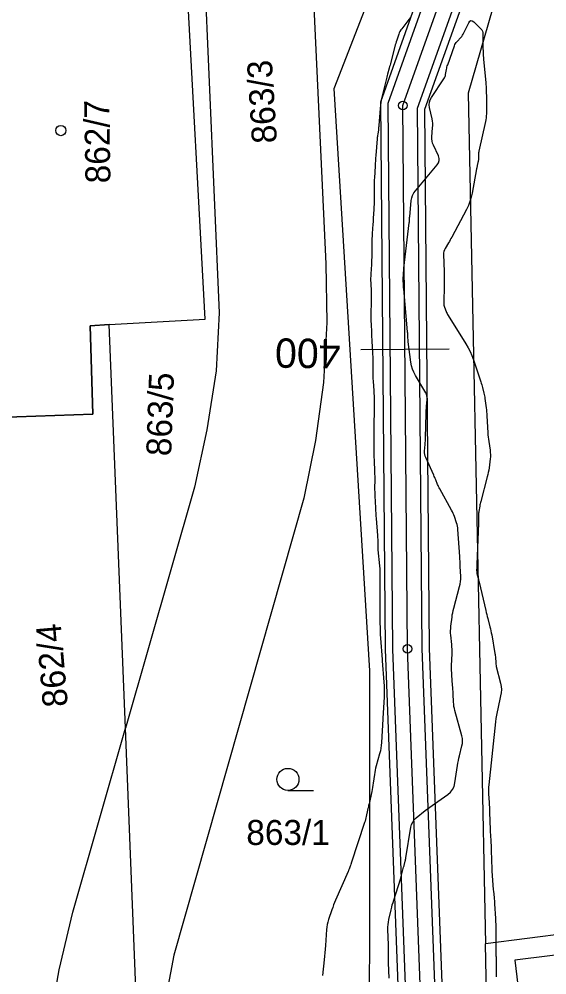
# Model space of a CAD drawing. Extents: x -534481 to -534256, y -1190577 to -1190138.
# Drawn here: x -534359.12 to -534341.14, y -1190186.56 to -1190154.02 of the extents above; entities that cross this region are included whole.
import ezdxf

# ---------------------------------------------------------------- set-up
doc = ezdxf.new("R2010")
doc.units = 0
for name, color, linetype in [('0_kroužky', 7, 'Continuous'), ('30', 7, 'Continuous'), ('31', 7, 'Continuous'), ('_N_osa', 7, 'Continuous'), ('_N_text', 7, 'Continuous'), ('_tenka', 7, 'Continuous'), ('Hranice parcel', 7, 'Continuous'), ('Parcelní čísla', 7, 'Continuous'), ('Polygon budovy', 7, 'Continuous'), ('Značky budov', 7, 'Continuous'), ('Značky kultur', 7, 'Continuous')]:
    doc.layers.add(name, color=color, linetype=linetype)

msp = doc.modelspace()

# ---------------------------------------------------------------- linework, layer by layer
at = {"layer": '0_kroužky'}
for centre in [(-534346.05, -1190156.962), (-534346.05, -1190156.962), (-534346.05, -1190156.962), (-534346.05, -1190156.962), (-534346.05, -1190156.962), (-534346.05, -1190156.962), (-534345.89, -1190175.458), (-534345.89, -1190175.458), (-534345.89, -1190175.458), (-534345.89, -1190175.458), (-534345.89, -1190175.458), (-534345.89, -1190175.458)]:
    msp.add_circle(centre, 0.15, dxfattribs=at)
at = {"layer": '30'}
msp.add_lwpolyline([(-534346.521, -1190186.667), (-534346.539, -1190186.147), (-534346.541, -1190186.096), (-534346.542, -1190186.045), (-534346.542, -1190185.994), (-534346.541, -1190185.943), (-534346.537, -1190185.739), (-534346.537, -1190185.688), (-534346.537, -1190185.637), (-534346.538, -1190185.586), (-534346.539, -1190185.535), (-534346.56, -1190185.016), (-534346.56, -1190184.93), (-534346.555, -1190184.846), (-534346.544, -1190184.761), (-534346.528, -1190184.678), (-534346.45, -1190184.344), (-534346.43, -1190184.26), (-534346.408, -1190184.177), (-534346.385, -1190184.095), (-534346.36, -1190184.013), (-534346.135, -1190183.297), (-534346.121, -1190183.253), (-534346.107, -1190183.208), (-534346.095, -1190183.162), (-534346.082, -1190183.117), (-534346.024, -1190182.898), (-534346.017, -1190182.871), (-534346.01, -1190182.844), (-534346.003, -1190182.818), (-534345.997, -1190182.791), (-534345.97, -1190182.684), (-534345.964, -1190182.657), (-534345.958, -1190182.63), (-534345.953, -1190182.603), (-534345.948, -1190182.576), (-534345.775, -1190181.533), (-534345.752, -1190181.441), (-534345.713, -1190181.357), (-534345.66, -1190181.282), (-534345.592, -1190181.216), (-534345.288, -1190180.968), (-534345.212, -1190180.907), (-534345.135, -1190180.848), (-534345.056, -1190180.789), (-534344.976, -1190180.733), (-534344.52, -1190180.416), (-534344.427, -1190180.338), (-534344.356, -1190180.247), (-534344.306, -1190180.143), (-534344.277, -1190180.026), (-534344.189, -1190179.436), (-534344.175, -1190179.351), (-534344.159, -1190179.266), (-534344.141, -1190179.181), (-534344.121, -1190179.097), (-534344.037, -1190178.761), (-534344.022, -1190178.677), (-534344.017, -1190178.593), (-534344.023, -1190178.509), (-534344.041, -1190178.425), (-534344.279, -1190177.556), (-534344.296, -1190177.487), (-534344.309, -1190177.417), (-534344.318, -1190177.346), (-534344.323, -1190177.275), (-534344.337, -1190176.988), (-534344.34, -1190176.916), (-534344.345, -1190176.845), (-534344.349, -1190176.773), (-534344.355, -1190176.701), (-534344.381, -1190176.356), (-534344.387, -1190176.275), (-534344.39, -1190176.193), (-534344.39, -1190176.112), (-534344.388, -1190176.03), (-534344.374, -1190175.628), (-534344.373, -1190175.549), (-534344.374, -1190175.471), (-534344.378, -1190175.392), (-534344.385, -1190175.314), (-534344.416, -1190174.999), (-534344.422, -1190174.922), (-534344.423, -1190174.845), (-534344.42, -1190174.768), (-534344.413, -1190174.691), (-534344.376, -1190174.383), (-534344.366, -1190174.307), (-534344.352, -1190174.231), (-534344.336, -1190174.155), (-534344.317, -1190174.08), (-534344.116, -1190173.339), (-534344.097, -1190173.255), (-534344.084, -1190173.171), (-534344.078, -1190173.086), (-534344.079, -1190173.001), (-534344.094, -1190172.657), (-534344.099, -1190172.571), (-534344.103, -1190172.485), (-534344.108, -1190172.4), (-534344.113, -1190172.314), (-534344.172, -1190171.396), (-534344.178, -1190171.339), (-534344.187, -1190171.282), (-534344.201, -1190171.227), (-534344.218, -1190171.172), (-534344.295, -1190170.954), (-534344.316, -1190170.9), (-534344.338, -1190170.846), (-534344.363, -1190170.794), (-534344.39, -1190170.743), (-534344.795, -1190170.01), (-534344.815, -1190169.973), (-534344.833, -1190169.936), (-534344.851, -1190169.898), (-534344.867, -1190169.859), (-534344.931, -1190169.703), (-534344.947, -1190169.664), (-534344.963, -1190169.626), (-534344.98, -1190169.587), (-534344.997, -1190169.549), (-534345.272, -1190168.95), (-534345.292, -1190168.896), (-534345.305, -1190168.842), (-534345.311, -1190168.786), (-534345.31, -1190168.729), (-534345.291, -1190168.499), (-534345.287, -1190168.441), (-534345.283, -1190168.383), (-534345.281, -1190168.325), (-534345.279, -1190168.268), (-534345.259, -1190167.454), (-534345.257, -1190167.393), (-534345.254, -1190167.332), (-534345.249, -1190167.271), (-534345.244, -1190167.21), (-534345.221, -1190166.966), (-534345.22, -1190166.906), (-534345.229, -1190166.849), (-534345.246, -1190166.793), (-534345.272, -1190166.739), (-534345.619, -1190166.153), (-534345.675, -1190166.045), (-534345.72, -1190165.934), (-534345.753, -1190165.819), (-534345.775, -1190165.7), (-534345.867, -1190165.004), (-534345.869, -1190164.988), (-534345.87, -1190164.972), (-534345.872, -1190164.956), (-534345.873, -1190164.94), (-534345.877, -1190164.876), (-534345.878, -1190164.86), (-534345.879, -1190164.844), (-534345.879, -1190164.829), (-534345.88, -1190164.813), (-534345.883, -1190164.739), (-534345.884, -1190164.721), (-534345.885, -1190164.703), (-534345.886, -1190164.686), (-534345.887, -1190164.668), (-534346.02, -1190163.199), (-534346.023, -1190163.164), (-534346.026, -1190163.128), (-534346.028, -1190163.093), (-534346.029, -1190163.057), (-534346.035, -1190162.914), (-534346.035, -1190162.879), (-534346.035, -1190162.845), (-534346.035, -1190162.81), (-534346.033, -1190162.775), (-534346.024, -1190162.637), (-534346.022, -1190162.602), (-534346.019, -1190162.568), (-534346.016, -1190162.533), (-534346.012, -1190162.499), (-534345.831, -1190160.952), (-534345.83, -1190160.941), (-534345.829, -1190160.93), (-534345.828, -1190160.919), (-534345.827, -1190160.909), (-534345.824, -1190160.864), (-534345.823, -1190160.844), (-534345.822, -1190160.825), (-534345.82, -1190160.787), (-534345.82, -1190160.778), (-534345.819, -1190160.768), (-534345.818, -1190160.759), (-534345.817, -1190160.749), (-534345.762, -1190160.199), (-534345.746, -1190160.107), (-534345.717, -1190160.02), (-534345.675, -1190159.939), (-534345.62, -1190159.863), (-534344.88, -1190158.985), (-534344.833, -1190158.913), (-534344.811, -1190158.838), (-534344.813, -1190158.76), (-534344.84, -1190158.678), (-534345.011, -1190158.317), (-534345.039, -1190158.247), (-534345.057, -1190158.174), (-534345.065, -1190158.1), (-534345.063, -1190158.025), (-534345.036, -1190157.718), (-534345.033, -1190157.641), (-534345.034, -1190157.565), (-534345.042, -1190157.49), (-534345.055, -1190157.414), (-534345.138, -1190157.025), (-534345.148, -1190156.936), (-534345.141, -1190156.851), (-534345.116, -1190156.769), (-534345.074, -1190156.691), (-534344.652, -1190156.052), (-534344.63, -1190156.016), (-534344.614, -1190155.979), (-534344.601, -1190155.94), (-534344.592, -1190155.9), (-534344.565, -1190155.735), (-534344.557, -1190155.694), (-534344.547, -1190155.653), (-534344.536, -1190155.613), (-534344.523, -1190155.574), (-534344.293, -1190154.931), (-534344.276, -1190154.889), (-534344.254, -1190154.849), (-534344.229, -1190154.812), (-534344.2, -1190154.777), (-534344.075, -1190154.642), (-534344.045, -1190154.607), (-534344.019, -1190154.571), (-534343.994, -1190154.532), (-534343.973, -1190154.492), (-534343.807, -1190154.144), (-534343.772, -1190154.093), (-534343.733, -1190154.07), (-534343.688, -1190154.077), (-534343.637, -1190154.114), (-534343.396, -1190154.347), (-534343.363, -1190154.386), (-534343.339, -1190154.429), (-534343.325, -1190154.476), (-534343.322, -1190154.527), (-534343.326, -1190154.739), (-534343.326, -1190154.792), (-534343.326, -1190154.844), (-534343.326, -1190154.897), (-534343.324, -1190154.95), (-534343.318, -1190155.166), (-534343.316, -1190155.219), (-534343.313, -1190155.273), (-534343.309, -1190155.326), (-534343.304, -1190155.38), (-534343.228, -1190156.185), (-534343.222, -1190156.251), (-534343.218, -1190156.317), (-534343.214, -1190156.383), (-534343.212, -1190156.449), (-534343.205, -1190156.713), (-534343.203, -1190156.779), (-534343.203, -1190156.845), (-534343.203, -1190156.91), (-534343.203, -1190156.976), (-534343.206, -1190157.246), (-534343.209, -1190157.313), (-534343.215, -1190157.379), (-534343.224, -1190157.445), (-534343.237, -1190157.51), (-534343.46, -1190158.51), (-534343.466, -1190158.543), (-534343.471, -1190158.576), (-534343.474, -1190158.609), (-534343.476, -1190158.643), (-534343.478, -1190158.789), (-534343.479, -1190158.817), (-534343.482, -1190158.844), (-534343.486, -1190158.871), (-534343.491, -1190158.899), (-534343.515, -1190159.007), (-534343.52, -1190159.034), (-534343.526, -1190159.061), (-534343.531, -1190159.088), (-534343.537, -1190159.116), (-534343.689, -1190159.94), (-534343.721, -1190160.085), (-534343.765, -1190160.226), (-534343.818, -1190160.363), (-534343.883, -1190160.496), (-534344.384, -1190161.439), (-534344.411, -1190161.488), (-534344.438, -1190161.537), (-534344.465, -1190161.586), (-534344.494, -1190161.634), (-534344.608, -1190161.826), (-534344.633, -1190161.875), (-534344.65, -1190161.927), (-534344.66, -1190161.979), (-534344.662, -1190162.034), (-534344.646, -1190162.616), (-534344.644, -1190162.73), (-534344.643, -1190162.845), (-534344.643, -1190162.959), (-534344.645, -1190163.074), (-534344.658, -1190163.685), (-534344.657, -1190163.722), (-534344.652, -1190163.759), (-534344.643, -1190163.795), (-534344.631, -1190163.831), (-534344.575, -1190163.971), (-534344.56, -1190164.006), (-534344.543, -1190164.04), (-534344.526, -1190164.073), (-534344.506, -1190164.105), (-534343.901, -1190165.08), (-534343.826, -1190165.209), (-534343.759, -1190165.341), (-534343.7, -1190165.477), (-534343.648, -1190165.616), (-534343.395, -1190166.372), (-534343.38, -1190166.419), (-534343.365, -1190166.466), (-534343.352, -1190166.513), (-534343.34, -1190166.56), (-534343.291, -1190166.75), (-534343.28, -1190166.797), (-534343.27, -1190166.845), (-534343.262, -1190166.893), (-534343.255, -1190166.942), (-534343.215, -1190167.254), (-534343.206, -1190167.322), (-534343.199, -1190167.391), (-534343.194, -1190167.459), (-534343.189, -1190167.528), (-534343.157, -1190168.1), (-534343.152, -1190168.175), (-534343.145, -1190168.25), (-534343.136, -1190168.324), (-534343.126, -1190168.399), (-534343.081, -1190168.696), (-534343.072, -1190168.77), (-534343.068, -1190168.845), (-534343.07, -1190168.919), (-534343.077, -1190168.994), (-534343.116, -1190169.301), (-534343.126, -1190169.377), (-534343.14, -1190169.452), (-534343.156, -1190169.527), (-534343.174, -1190169.601), (-534343.396, -1190170.439), (-534343.406, -1190170.479), (-534343.415, -1190170.519), (-534343.423, -1190170.56), (-534343.431, -1190170.6), (-534343.459, -1190170.778), (-534343.464, -1190170.811), (-534343.468, -1190170.845), (-534343.47, -1190170.878), (-534343.471, -1190170.912), (-534343.474, -1190171.046), (-534343.475, -1190171.079), (-534343.475, -1190171.112), (-534343.476, -1190171.146), (-534343.478, -1190171.179), (-534343.531, -1190172.583), (-534343.532, -1190172.609), (-534343.533, -1190172.635), (-534343.534, -1190172.661), (-534343.535, -1190172.687), (-534343.537, -1190172.792), (-534343.536, -1190172.818), (-534343.534, -1190172.844), (-534343.531, -1190172.87), (-534343.525, -1190172.895), (-534343.487, -1190173.049), (-534343.478, -1190173.084), (-534343.47, -1190173.118), (-534343.462, -1190173.152), (-534343.454, -1190173.186), (-534343.225, -1190174.155), (-534343.208, -1190174.224), (-534343.191, -1190174.293), (-534343.174, -1190174.362), (-534343.157, -1190174.431), (-534343.086, -1190174.707), (-534343.069, -1190174.776), (-534343.053, -1190174.845), (-534343.039, -1190174.915), (-534343.025, -1190174.985), (-534342.912, -1190175.616), (-534342.906, -1190175.652), (-534342.901, -1190175.689), (-534342.898, -1190175.726), (-534342.895, -1190175.763), (-534342.888, -1190175.912), (-534342.886, -1190175.949), (-534342.881, -1190175.986), (-534342.875, -1190176.022), (-534342.867, -1190176.059), (-534342.724, -1190176.63), (-534342.703, -1190176.737), (-534342.696, -1190176.845), (-534342.701, -1190176.952), (-534342.72, -1190177.06), (-534342.82, -1190177.499), (-534342.843, -1190177.609), (-534342.864, -1190177.719), (-534342.881, -1190177.829), (-534342.894, -1190177.94), (-534343.127, -1190180.095), (-534343.133, -1190180.17), (-534343.136, -1190180.245), (-534343.136, -1190180.32), (-534343.132, -1190180.395), (-534343.11, -1190180.695), (-534343.105, -1190180.77), (-534343.101, -1190180.845), (-534343.098, -1190180.92), (-534343.095, -1190180.995), (-534343.085, -1190181.347), (-534343.083, -1190181.427), (-534343.08, -1190181.507), (-534343.076, -1190181.587), (-534343.072, -1190181.667), (-534343.054, -1190181.987), (-534343.05, -1190182.067), (-534343.047, -1190182.147), (-534343.044, -1190182.227), (-534343.041, -1190182.307), (-534343.032, -1190182.67), (-534343.029, -1190182.757), (-534343.025, -1190182.844), (-534343.021, -1190182.932), (-534343.016, -1190183.019), (-534342.987, -1190183.501), (-534342.983, -1190183.554), (-534342.979, -1190183.607), (-534342.974, -1190183.66), (-534342.968, -1190183.714), (-534342.943, -1190183.926), (-534342.938, -1190183.979), (-534342.933, -1190184.033), (-534342.928, -1190184.086), (-534342.925, -1190184.139), (-534342.898, -1190184.641), (-534342.893, -1190184.743), (-534342.889, -1190184.845), (-534342.886, -1190184.946), (-534342.885, -1190185.048), (-534342.881, -1190185.639), (-534342.881, -1190185.673), (-534342.88, -1190185.707), (-534342.88, -1190185.741), (-534342.88, -1190185.775), (-534342.878, -1190185.91), (-534342.877, -1190185.944), (-534342.877, -1190185.978), (-534342.876, -1190186.012), (-534342.876, -1190186.046), (-534342.872, -1190186.628)], dxfattribs=at)
at = {"layer": '31'}
msp.add_lwpolyline([(-534345.794, -1190153.964), (-534345.846, -1190154.031), (-534346.089, -1190154.346), (-534346.12, -1190154.39), (-534346.147, -1190154.436), (-534346.171, -1190154.485), (-534346.19, -1190154.535), (-534346.26, -1190154.741), (-534346.277, -1190154.793), (-534346.294, -1190154.845), (-534346.309, -1190154.897), (-534346.323, -1190154.95), (-534346.461, -1190155.487), (-534346.474, -1190155.538), (-534346.487, -1190155.588), (-534346.501, -1190155.638), (-534346.514, -1190155.689), (-534346.569, -1190155.89), (-534346.583, -1190155.94), (-534346.596, -1190155.991), (-534346.609, -1190156.041), (-534346.622, -1190156.092), (-534346.755, -1190156.633), (-534346.779, -1190156.739), (-534346.798, -1190156.846), (-534346.813, -1190156.954), (-534346.824, -1190157.062), (-534346.867, -1190157.638), (-534346.87, -1190157.676), (-534346.874, -1190157.715), (-534346.879, -1190157.753), (-534346.884, -1190157.791), (-534346.906, -1190157.942), (-534346.911, -1190157.98), (-534346.916, -1190158.018), (-534346.92, -1190158.056), (-534346.923, -1190158.094), (-534346.972, -1190158.666), (-534346.98, -1190158.755), (-534346.986, -1190158.845), (-534346.992, -1190158.934), (-534346.997, -1190159.024), (-534347.018, -1190159.421), (-534347.021, -1190159.491), (-534347.024, -1190159.562), (-534347.025, -1190159.633), (-534347.026, -1190159.703), (-534347.026, -1190159.986), (-534347.026, -1190160.056), (-534347.027, -1190160.127), (-534347.029, -1190160.198), (-534347.032, -1190160.268), (-534347.052, -1190160.684), (-534347.056, -1190160.764), (-534347.061, -1190160.844), (-534347.066, -1190160.924), (-534347.071, -1190161.004), (-534347.092, -1190161.324), (-534347.097, -1190161.404), (-534347.101, -1190161.484), (-534347.104, -1190161.564), (-534347.105, -1190161.645), (-534347.11, -1190162.055), (-534347.111, -1190162.134), (-534347.114, -1190162.213), (-534347.117, -1190162.292), (-534347.121, -1190162.371), (-534347.141, -1190162.691), (-534347.145, -1190162.768), (-534347.147, -1190162.845), (-534347.147, -1190162.921), (-534347.145, -1190162.998), (-534347.134, -1190163.306), (-534347.132, -1190163.382), (-534347.13, -1190163.459), (-534347.13, -1190163.536), (-534347.131, -1190163.613), (-534347.138, -1190164.091), (-534347.139, -1190164.166), (-534347.138, -1190164.242), (-534347.137, -1190164.317), (-534347.134, -1190164.392), (-534347.122, -1190164.694), (-534347.119, -1190164.769), (-534347.115, -1190164.844), (-534347.111, -1190164.92), (-534347.107, -1190164.995), (-534347.085, -1190165.347), (-534347.081, -1190165.43), (-534347.077, -1190165.513), (-534347.076, -1190165.596), (-534347.075, -1190165.679), (-534347.075, -1190166.01), (-534347.074, -1190166.093), (-534347.072, -1190166.176), (-534347.068, -1190166.259), (-534347.063, -1190166.342), (-534347.04, -1190166.677), (-534347.034, -1190166.761), (-534347.031, -1190166.845), (-534347.029, -1190166.928), (-534347.029, -1190167.012), (-534347.032, -1190167.483), (-534347.033, -1190167.701), (-534347.036, -1190168.065), (-534347.037, -1190168.21), (-534347.037, -1190168.283), (-534347.039, -1190168.668), (-534347.039, -1190168.756), (-534347.038, -1190168.844), (-534347.036, -1190168.933), (-534347.032, -1190169.021), (-534347.012, -1190169.449), (-534347.01, -1190169.515), (-534347.008, -1190169.581), (-534347.007, -1190169.648), (-534347.007, -1190169.714), (-534347.01, -1190169.98), (-534347.01, -1190170.046), (-534347.009, -1190170.112), (-534347.007, -1190170.179), (-534347.004, -1190170.245), (-534346.982, -1190170.661), (-534346.977, -1190170.753), (-534346.972, -1190170.844), (-534346.965, -1190170.936), (-534346.958, -1190171.027), (-534346.913, -1190171.599), (-534346.91, -1190171.64), (-534346.908, -1190171.681), (-534346.907, -1190171.722), (-534346.907, -1190171.763), (-534346.907, -1190171.926), (-534346.906, -1190171.967), (-534346.905, -1190172.008), (-534346.902, -1190172.049), (-534346.899, -1190172.09), (-534346.848, -1190172.635), (-534346.839, -1190172.74), (-534346.833, -1190172.845), (-534346.829, -1190172.95), (-534346.828, -1190173.055), (-534346.828, -1190174.597), (-534346.827, -1190174.721), (-534346.824, -1190174.844), (-534346.818, -1190174.968), (-534346.81, -1190175.091), (-534346.757, -1190175.824), (-534346.757, -1190175.834), (-534346.756, -1190175.855), (-534346.756, -1190175.865), (-534346.694, -1190176.598), (-534346.685, -1190176.721), (-534346.682, -1190176.845), (-534346.682, -1190176.968), (-534346.687, -1190177.092), (-534346.731, -1190177.828), (-534346.732, -1190177.838), (-534346.734, -1190177.854), (-534346.734, -1190177.859), (-534346.777, -1190178.651), (-534346.784, -1190178.747), (-534346.798, -1190178.843), (-534346.816, -1190178.937), (-534346.84, -1190179.031), (-534346.957, -1190179.448), (-534346.976, -1190179.519), (-534346.992, -1190179.591), (-534347.006, -1190179.664), (-534347.017, -1190179.737), (-534347.057, -1190180.031), (-534347.067, -1190180.104), (-534347.079, -1190180.177), (-534347.093, -1190180.25), (-534347.109, -1190180.322), (-534347.202, -1190180.738), (-534347.214, -1190180.791), (-534347.225, -1190180.845), (-534347.237, -1190180.898), (-534347.248, -1190180.951), (-534347.294, -1190181.164), (-534347.307, -1190181.217), (-534347.32, -1190181.269), (-534347.335, -1190181.322), (-534347.351, -1190181.374), (-534347.806, -1190182.759), (-534347.812, -1190182.776), (-534347.818, -1190182.793), (-534347.834, -1190182.836), (-534347.84, -1190182.853), (-534347.844, -1190182.861), (-534347.883, -1190182.961), (-534347.89, -1190182.98), (-534347.898, -1190182.999), (-534347.906, -1190183.018), (-534347.914, -1190183.037), (-534348.339, -1190184.017), (-534348.373, -1190184.098), (-534348.406, -1190184.18), (-534348.437, -1190184.262), (-534348.467, -1190184.345), (-534348.582, -1190184.678), (-534348.608, -1190184.762), (-534348.628, -1190184.847), (-534348.642, -1190184.933), (-534348.651, -1190185.02), (-534348.687, -1190185.565), (-534348.696, -1190185.685), (-534348.706, -1190185.804), (-534348.717, -1190185.924), (-534348.73, -1190186.044), (-534348.789, -1190186.585)], dxfattribs=at)
at = {"layer": '_N_osa'}
msp.add_lwpolyline([(-534342.428, -1190234.65), (-534342.865, -1190226.62), (-534344.323, -1190207.198), (-534345.257, -1190192.285), (-534345.89, -1190175.458), (-534346.05, -1190156.962), (-534344.257, -1190151.926), (-534342.463, -1190149.215)], dxfattribs=at)
at = {"layer": '_N_text'}
msp.add_lwpolyline([(-534344.478, -1190165.258), (-534347.478, -1190165.284)], dxfattribs=at)
at = {"layer": '_tenka'}
for points in [[(-534343.317, -1190232.109), (-534343.613, -1190226.668), (-534345.072, -1190207.25), (-534346.006, -1190192.323), (-534346.64, -1190175.475), (-534346.801, -1190156.835), (-534344.933, -1190151.588), (-534343.268, -1190149.073)], [(-534343.067, -1190232.098), (-534343.364, -1190226.652), (-534344.822, -1190207.233), (-534345.756, -1190192.31), (-534346.39, -1190175.47), (-534346.551, -1190156.878), (-534344.708, -1190151.701), (-534343, -1190149.12)], [(-534342.068, -1190232.057), (-534342.366, -1190226.587), (-534343.825, -1190207.164), (-534344.757, -1190192.26), (-534345.39, -1190175.446), (-534345.55, -1190157.046), (-534343.807, -1190152.151), (-534341.926, -1190149.309)], [(-534341.818, -1190232.046), (-534342.116, -1190226.571), (-534343.575, -1190207.147), (-534344.507, -1190192.248), (-534345.14, -1190175.441), (-534345.299, -1190157.088), (-534343.581, -1190152.264), (-534341.657, -1190149.357)]]:
    msp.add_lwpolyline(points, dxfattribs=at)
at = {"layer": 'Hranice parcel'}
for p, q in [((-534355.5, -1190178.16), (-534356.05, -1190164.42)), ((-534354.73, -1190197.08), (-534355.5, -1190178.16)), ((-534334.79, -1190184.43), (-534343.24, -1190185.5))]:
    msp.add_line(p, q, dxfattribs=at)
for points in [[(-534349.263, -1190148.015), (-534349.33, -1190148.26), (-534348.67, -1190162.35), (-534348.64, -1190164.35), (-534348.75, -1190166.39), (-534349.02, -1190168.37), (-534349.42, -1190170.33), (-534353.85, -1190185.89), (-534354.6, -1190189.86), (-534354.75, -1190192.89), (-534354.73, -1190197.08)], [(-534347.19, -1190196.18), (-534347.17, -1190176.21), (-534348.39, -1190156.38), (-534345.398, -1190148.697)], [(-534341.743, -1190149.341), (-534343.82, -1190156.54), (-534343.24, -1190185.5)], [(-534356.05, -1190164.42), (-534352.78, -1190164.24), (-534353.43, -1190152.26)], [(-534353.43, -1190152.26), (-534352.82, -1190152.23), (-534352.3, -1190164.02), (-534352.41, -1190166), (-534352.72, -1190168), (-534353.15, -1190169.96), (-534355.5, -1190178.16)], [(-534356.05, -1190164.42), (-534356.7, -1190164.46), (-534356.61, -1190167.47), (-534359.85, -1190167.58), (-534360.62, -1190167.61)], [(-534358.42, -1190197.47), (-534358.38, -1190192.4), (-534358.3, -1190190.41), (-534358.1, -1190188.37), (-534357.75, -1190186.39), (-534357.29, -1190184.43), (-534355.5, -1190178.16)], [(-534340.96, -1190232.41), (-534341.05, -1190227.37), (-534341.07, -1190226.16), (-534342.47, -1190212), (-534343.03, -1190195.73), (-534343.24, -1190185.5)]]:
    msp.add_lwpolyline(points, dxfattribs=at)
at = {"layer": 'Polygon budovy'}
for points in [[(-534359.85, -1190167.58), (-534356.61, -1190167.47), (-534356.7, -1190164.46), (-534356.05, -1190164.42), (-534352.78, -1190164.24), (-534353.43, -1190152.26), (-534353.54, -1190152.27), (-534356.53, -1190152.42), (-534360.66, -1190152.64)], [(-534325.28, -1190183.96), (-534342.24, -1190186.06), (-534341.16, -1190195.04), (-534330.16, -1190193.66), (-534328.97, -1190203.08), (-534323, -1190202.33)]]:
    msp.add_lwpolyline(points, close=True, dxfattribs=at)
at = {"layer": 'Značky budov'}
msp.add_circle((-534357.697, -1190157.813), 0.175, dxfattribs=at)
at = {"layer": 'Značky kultur'}
msp.add_line((-534349.965, -1190180.279), (-534349.09, -1190180.279), dxfattribs=at)
msp.add_circle((-534349.965, -1190179.904), 0.375, dxfattribs=at)

# ---------------------------------------------------------------- texts
at = {"layer": '_N_text'}
msp.add_text('400', height=1, rotation=179.271, dxfattribs=at).set_placement((-534348.165, -1190164.914))
at = {"layer": 'Parcelní čísla'}
for s, rotation, p in [('863/3', 93.6145, (-534350.334, -1190158.227)), ('862/7', 91, (-534356.005, -1190159.605)), ('863/5', 88, (-534353.941, -1190168.909)), ('862/4', 95, (-534357.454, -1190177.406))]:
    msp.add_text(s, height=0.85, rotation=rotation, dxfattribs=at).set_placement(p)
msp.add_text('863/1', height=0.85, dxfattribs=at).set_placement((-534351.381, -1190182.136))

doc.saveas('drawing.dxf')
